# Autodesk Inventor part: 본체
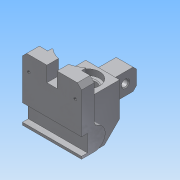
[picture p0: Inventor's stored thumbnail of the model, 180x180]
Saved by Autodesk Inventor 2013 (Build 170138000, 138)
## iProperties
Created: 2016-11
Part Number: 본체
Material: 알루미늄 6061
Document SubType Name: Modeling
Designer: Administrator
Density: 2.71 g/cm^3
Mass: 462.697 g
Surface Area: 317.767 cm^2
Volume: 170.737 cm^3
Author: Administrator
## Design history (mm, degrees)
sketch "스케치1"
  geometry: L1 (-20, 18)-(0, 18); L2 (0, 18)-(0, -30); L3 (0, -30)-(-20, -30); L4 (-20, -30)-(-20, 18); 2 further points
  constraints: 8 end point, 2 parallel, 1 coincident, 1 horizontal, 1 perpendicular, 1 vertical alignment
  dimensions: "d3" = 20 distance of L1.start L1.end; "d5" = 30 distance from line of point (0, 0) L3; "d7" = 48 distance of L3.end L1.start
extrude "돌출1" new body sketch "스케치1" distance "d8" = 28; taper "d9" = 0 deg
sketch "스케치2"
  geometry: L1 (20, 18)-(0, 18) reference; L2 (0, 18)-(0, -30) reference; L3 (0, -30)-(20, -30) reference; L4 (20, -30)-(20, 18) reference; 1 further point
extrude "돌출2" join sketch "스케치2" distance "d10" = 30; taper "d11" = 0 deg
sketch "스케치3"
  geometry: 2 further points
  constraints: 1 coincident
hole "구멍1" sketch "스케치3" at (0, 0) diameter "d12" = 20; stored, may be unused: countersink angle "d16" = 90 deg, drill point angle "d18" = 118 deg; dims "d13" = 6, "d14" = 29, "d15" = 7, "d17" = 8
sketch "스케치4"
  geometry: L1 (-58, 48)-(0, 48) reference; L2 (-58, 0)-(-58, 48) reference; L3 (-58, 30)-(-40, 48); 1 further point
  constraints: 2 end point, 2 point on line
  dimensions: "d19" = 45 deg angle of L2 L3; "d20" = 18 distance from line of L3.end L2
extrude "돌출3" cut sketch "스케치4" distance "d21" = 30; taper "d22" = 0 deg
sketch "스케치6"
  geometry: L1 (20, 0)-(0, 0) reference; L2 (10, 30)-(20, 30); L3 (20, 30)-(20, 5); L4 (20, 5)-(10, 5); L5 (10, 5)-(10, 30); 2 further points
  constraints: 8 end point, 2 parallel, 1 horizontal, 1 perpendicular, 1 vertical alignment
  dimensions: "d27" = 25 distance of L4.end L2.start; "d29" = 10 distance of L2.start L2.end; "d30" = 5 distance between parallel lines of L4 L1
extrude "돌출4" join sketch "스케치6" distance "d31" = 30; taper "d32" = 0 deg
sketch "스케치7"
  geometry: L1 (0, 30)-(25, 30) reference; L2 (0, 0)-(0, 30) reference; 2 further points
  dimensions: "d33" = 12.5 distance from line of point (12.5, 17) L2; "d34" = 13 distance from line of point (12.5, 17) L1
hole "구멍2" sketch "스케치7" at (12.5, 17) diameter "d35" = 8; stored, may be unused: countersink angle "d39" = 90 deg, drill point angle "d41" = 118 deg; dims "d36" = 6, "d37" = 29, "d38" = 7, "d40" = 8
chamfer "모따기1" distance "d42" = 4; stored, may be unused: second distance "d43" = 2, angle "d44" = 45 deg
sketch "스케치8"
  geometry: L1 (-58, 4)-(-58, 30) reference; L2 (-18, 3)-(32, 3); L3 (32, 3)-(32, -12); L4 (-44, -12)-(-44, 3); L5 (-41, -12)-(-41, -5); L6 (-41, -5)-(-21, -5); L7 (-21, -5)-(-21, -12); L8 (32, -12)-(-21, -12); L9 (-41, -12)-(-44, -12); C1 r 4 at (-17.5, 65) reference; A1 r 13 centre (-31, 3) between (-18, 3) and (-44, 3); 1 further point
  constraints: 16 end point, 5 parallel, 4 perpendicular, 2 point on circle, 1 centre point, 1 horizontal, 1 horizontal alignment, 1 tangent
  dimensions: "d45" = 26 diameter of A1; "d46" = 15 distance of L2.end L3.end; "d48" = 63 distance from line of A1.centre L3; "d49" = 90 distance between parallel lines of L3 L1; "d50" = 7 distance of L5.start L5.end; "d51" = 3 distance of L5.start L4.start; "d52" = 20 distance of L5.end L6.end; "d53" = 77 distance from line of L8 C1.centre
extrude "돌출5" join sketch "스케치8" distance "d54" = 15; taper "d55" = 0 deg; dims "d56" = 20, "d57" = 0
fillet "모깎기1" dims "d58" = 5, "d59" = 3
chamfer "모따기2" distance "d60" = 1; stored, may be unused: second distance "d61" = 2, angle "d62" = 45 deg
sketch "스케치9"
  geometry: L1 (35, 0)-(0, 0) reference; L2 (35, 32)-(35, 0) reference; 3 further points
  dimensions: "d63" = 18 distance from line of point (7.5, 18) L1; "d64" = 27.5 distance from line of L2 point (7.5, 18)
hole "구멍3" sketch "스케치9" at (7.5, 18) diameter "d65" = 3.242; stored, may be unused: countersink angle "d69" = 90 deg, drill point angle "d71" = 118 deg; dims "d66" = 6, "d67" = 29, "d68" = 7, "d70" = 8
chamfer "모따기3" distance "d72" = 5; stored, may be unused: second distance "d73" = 2, angle "d74" = 45 deg
sketch "스케치5"
  geometry: L1 (0, 48)-(0, 0) reference; L2 (-40, 48)-(0, 48) reference; 2 further points
  constraints: 1 other
  dimensions: "d23" = 25 distance from line of point (-25, 30) L1; "d24" = 18 distance from line of point (-25, 30) L2
feature "엠보싱1" sketch "스케치5" dims "d3" = 20, "d5" = 30, "d7" = 48, "d25" = 0.5, "d26" = 0
sketch "스케치10"
  geometry: L1 (20, 18)-(20, -27) reference; L2 (-20, 18)-(-20, -27) reference; L3 (-20, -22)-(20, -22); L4 (20, -22)-(20, -27); L5 (20, -27)-(-20, -27); L6 (-20, -27)-(-20, -22); 1 further point
  constraints: 8 end point, 2 parallel, 2 point on line, 1 horizontal, 1 horizontal alignment, 1 midpoint, 1 perpendicular, 1 vertical alignment
  dimensions: "d75" = 5 distance of L3.end L4.end
extrude "돌출6" join sketch "스케치10" stored distance "d77" = 10; taper "d78" = 0 deg
sketch "스케치11"
  geometry: L1 (0, -15)-(60, -15) reference; L2 (10, 5)-(50, 5) reference; L3 (10, 0)-(0, 0) reference; L4 (24, -15)-(24, -1.373); L5 (36, -15)-(36, -1.373); A1 r 29 centre (30, 27) between (11.106, 5) and (24, -1.373); A2 r 29 centre (30, 27) between (48.894, 5) and (11.106, 5); A3 r 29 centre (30, 27) between (24, -1.373) and (36, -1.373); A4 r 29 centre (30, 27) between (36, -1.373) and (48.894, 5); 1 further point
  constraints: 9 point on circle, 4 centre point, 4 end point, 4 point on line, 1 coincident, 1 parallel, 1 perpendicular
  dimensions: "d79" = 29 radius of A1; "d80" = 12 distance between parallel lines of L5 L4; "d81" = 6 distance from line of point (30, 27) L5
extrude "돌출7" cut sketch "스케치11" distance "d82" = 18; taper "d83" = 0 deg
node "솔리드1"
mirror "대칭1"
